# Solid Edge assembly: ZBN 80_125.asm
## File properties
Title: Zylinder
Author: bmolnar
Template: iso metric assembly.asm
Last saved by: bmolnar
Revision: 20
Application: Solid Edge
Username: bmolnar
Dokumentum tartalom típus: 1
Document Number: ZBN 80/125
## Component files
Profilrohr.par
Kolbenstange.par
Kit.par
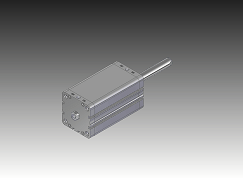
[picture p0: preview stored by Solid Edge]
